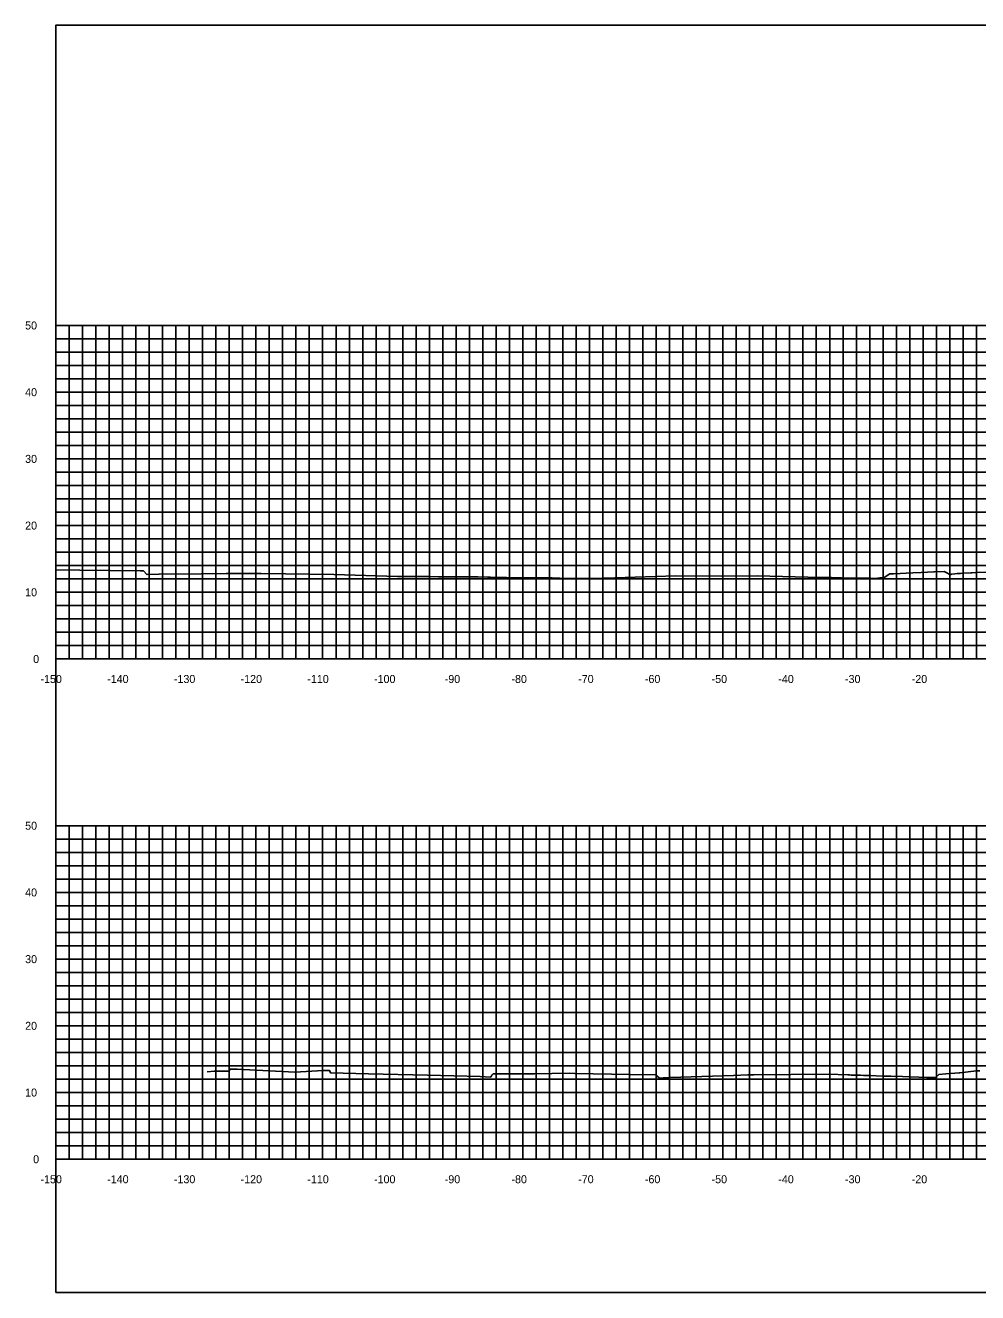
# Model space of a CAD drawing. Extents: x 1797714 to 1804825, y 249015 to 250269.
# Drawn here: x 1804149.6 to 1804292.3, y 249628.2 to 249818.2 of the extents above; entities that cross this region are included whole.
import ezdxf

# ---------------------------------------------------------------- set-up
doc = ezdxf.new("R2010")
doc.units = 0
for name, color, linetype in [('10', 7, 'Continuous'), ('31', 7, 'Continuous'), ('60', 7, 'Continuous'), ('Level 62', 7, 'Continuous'), ('M-ROADS', 7, 'Continuous')]:
    doc.layers.add(name, color=color, linetype=linetype)

msp = doc.modelspace()

# ---------------------------------------------------------------- linework, layer by layer
msp.add_lwpolyline([(1804154.16, 249628.17), (1804454.16, 249628.17), (1804454.16, 249818.17), (1804154.16, 249818.17)], close=True)
at = {"layer": '60'}
for p, q in [((1804154.1, 249773.17), (1804154.16, 249773.17)), ((1804154.16, 249723.17), (1804154.16, 249773.17)), ((1804154.1, 249763.17), (1804154.16, 249763.17)), ((1804154.1, 249753.17), (1804154.16, 249753.17)), ((1804154.1, 249743.17), (1804154.16, 249743.17)), ((1804154.1, 249733.17), (1804154.16, 249733.17)), ((1804154.1, 249723.17), (1804154.16, 249723.17)), ((1804154.16, 249723.17), (1804454.16, 249723.17)), ((1804154.16, 249723.11), (1804154.16, 249723.17)), ((1804164.16, 249723.11), (1804164.16, 249723.17)), ((1804174.16, 249723.11), (1804174.16, 249723.17)), ((1804184.16, 249723.11), (1804184.16, 249723.17)), ((1804194.16, 249723.11), (1804194.16, 249723.17)), ((1804204.16, 249723.11), (1804204.16, 249723.17)), ((1804214.16, 249723.11), (1804214.16, 249723.17)), ((1804224.16, 249723.11), (1804224.16, 249723.17)), ((1804234.16, 249723.11), (1804234.16, 249723.17)), ((1804244.16, 249723.11), (1804244.16, 249723.17)), ((1804254.16, 249723.11), (1804254.16, 249723.17)), ((1804264.16, 249723.11), (1804264.16, 249723.17)), ((1804274.16, 249723.11), (1804274.16, 249723.17)), ((1804284.16, 249723.11), (1804284.16, 249723.17)), ((1804154.1, 249698.17), (1804154.16, 249698.17)), ((1804154.16, 249648.17), (1804154.16, 249698.17)), ((1804154.1, 249688.17), (1804154.16, 249688.17)), ((1804154.1, 249678.17), (1804154.16, 249678.17)), ((1804154.1, 249668.17), (1804154.16, 249668.17)), ((1804154.1, 249658.17), (1804154.16, 249658.17)), ((1804154.1, 249648.17), (1804154.16, 249648.17)), ((1804154.16, 249648.17), (1804454.16, 249648.17)), ((1804154.16, 249648.11), (1804154.16, 249648.17)), ((1804164.16, 249648.11), (1804164.16, 249648.17)), ((1804174.16, 249648.11), (1804174.16, 249648.17)), ((1804184.16, 249648.11), (1804184.16, 249648.17)), ((1804194.16, 249648.11), (1804194.16, 249648.17)), ((1804204.16, 249648.11), (1804204.16, 249648.17)), ((1804214.16, 249648.11), (1804214.16, 249648.17)), ((1804224.16, 249648.11), (1804224.16, 249648.17)), ((1804234.16, 249648.11), (1804234.16, 249648.17)), ((1804244.16, 249648.11), (1804244.16, 249648.17)), ((1804254.16, 249648.11), (1804254.16, 249648.17)), ((1804264.16, 249648.11), (1804264.16, 249648.17)), ((1804274.16, 249648.11), (1804274.16, 249648.17)), ((1804284.16, 249648.11), (1804284.16, 249648.17))]:
    msp.add_line(p, q, dxfattribs=at)
at = {"layer": 'Level 62'}
for p, q in [((1804154.16, 249773.17), (1804454.16, 249773.17)), ((1804154.16, 249723.17), (1804154.16, 249773.17)), ((1804156.16, 249723.17), (1804156.16, 249773.17)), ((1804158.16, 249723.17), (1804158.16, 249773.17)), ((1804160.16, 249723.17), (1804160.16, 249773.17)), ((1804162.16, 249723.17), (1804162.16, 249773.17)), ((1804164.16, 249723.17), (1804164.16, 249773.17)), ((1804166.16, 249723.17), (1804166.16, 249773.17)), ((1804168.16, 249723.17), (1804168.16, 249773.17)), ((1804170.16, 249723.17), (1804170.16, 249773.17)), ((1804172.16, 249723.17), (1804172.16, 249773.17)), ((1804174.16, 249723.17), (1804174.16, 249773.17)), ((1804176.16, 249723.17), (1804176.16, 249773.17)), ((1804178.16, 249723.17), (1804178.16, 249773.17)), ((1804180.16, 249723.17), (1804180.16, 249773.17)), ((1804182.16, 249723.17), (1804182.16, 249773.17)), ((1804184.16, 249723.17), (1804184.16, 249773.17)), ((1804186.16, 249723.17), (1804186.16, 249773.17)), ((1804188.16, 249723.17), (1804188.16, 249773.17)), ((1804190.16, 249723.17), (1804190.16, 249773.17)), ((1804192.16, 249723.17), (1804192.16, 249773.17)), ((1804194.16, 249723.17), (1804194.16, 249773.17)), ((1804196.16, 249723.17), (1804196.16, 249773.17)), ((1804198.16, 249723.17), (1804198.16, 249773.17)), ((1804200.16, 249723.17), (1804200.16, 249773.17)), ((1804202.16, 249723.17), (1804202.16, 249773.17)), ((1804204.16, 249723.17), (1804204.16, 249773.17)), ((1804206.16, 249723.17), (1804206.16, 249773.17)), ((1804208.16, 249723.17), (1804208.16, 249773.17)), ((1804210.16, 249723.17), (1804210.16, 249773.17)), ((1804212.16, 249723.17), (1804212.16, 249773.17)), ((1804214.16, 249723.17), (1804214.16, 249773.17)), ((1804216.16, 249723.17), (1804216.16, 249773.17)), ((1804218.16, 249723.17), (1804218.16, 249773.17)), ((1804220.16, 249723.17), (1804220.16, 249773.17)), ((1804222.16, 249723.17), (1804222.16, 249773.17)), ((1804224.16, 249723.17), (1804224.16, 249773.17)), ((1804226.16, 249723.17), (1804226.16, 249773.17)), ((1804228.16, 249723.17), (1804228.16, 249773.17)), ((1804230.16, 249723.17), (1804230.16, 249773.17)), ((1804232.16, 249723.17), (1804232.16, 249773.17)), ((1804234.16, 249723.17), (1804234.16, 249773.17)), ((1804236.16, 249723.17), (1804236.16, 249773.17)), ((1804238.16, 249723.17), (1804238.16, 249773.17)), ((1804240.16, 249723.17), (1804240.16, 249773.17)), ((1804242.16, 249723.17), (1804242.16, 249773.17)), ((1804244.16, 249723.17), (1804244.16, 249773.17)), ((1804246.16, 249723.17), (1804246.16, 249773.17)), ((1804248.16, 249723.17), (1804248.16, 249773.17)), ((1804250.16, 249723.17), (1804250.16, 249773.17)), ((1804252.16, 249723.17), (1804252.16, 249773.17)), ((1804254.16, 249723.17), (1804254.16, 249773.17)), ((1804256.16, 249723.17), (1804256.16, 249773.17)), ((1804258.16, 249723.17), (1804258.16, 249773.17)), ((1804260.16, 249723.17), (1804260.16, 249773.17)), ((1804262.16, 249723.17), (1804262.16, 249773.17)), ((1804264.16, 249723.17), (1804264.16, 249773.17)), ((1804266.16, 249723.17), (1804266.16, 249773.17)), ((1804268.16, 249723.17), (1804268.16, 249773.17)), ((1804270.16, 249723.17), (1804270.16, 249773.17)), ((1804272.16, 249723.17), (1804272.16, 249773.17)), ((1804274.16, 249723.17), (1804274.16, 249773.17)), ((1804276.16, 249723.17), (1804276.16, 249773.17)), ((1804278.16, 249723.17), (1804278.16, 249773.17)), ((1804280.16, 249723.17), (1804280.16, 249773.17)), ((1804282.16, 249723.17), (1804282.16, 249773.17)), ((1804284.16, 249723.17), (1804284.16, 249773.17)), ((1804286.16, 249723.17), (1804286.16, 249773.17)), ((1804288.16, 249723.17), (1804288.16, 249773.17)), ((1804290.16, 249723.17), (1804290.16, 249773.17)), ((1804292.16, 249723.17), (1804292.16, 249773.17)), ((1804154.16, 249771.17), (1804454.16, 249771.17)), ((1804154.16, 249769.17), (1804454.16, 249769.17)), ((1804154.16, 249767.17), (1804454.16, 249767.17)), ((1804154.16, 249765.17), (1804454.16, 249765.17)), ((1804154.16, 249763.17), (1804454.16, 249763.17)), ((1804154.16, 249761.17), (1804454.16, 249761.17)), ((1804154.16, 249759.17), (1804454.16, 249759.17)), ((1804154.16, 249757.17), (1804454.16, 249757.17)), ((1804154.16, 249755.17), (1804454.16, 249755.17)), ((1804154.16, 249753.17), (1804454.16, 249753.17)), ((1804154.16, 249751.17), (1804454.16, 249751.17)), ((1804154.16, 249749.17), (1804454.16, 249749.17)), ((1804154.16, 249747.17), (1804454.16, 249747.17)), ((1804154.16, 249745.17), (1804454.16, 249745.17)), ((1804154.16, 249743.17), (1804454.16, 249743.17)), ((1804154.16, 249741.17), (1804454.16, 249741.17)), ((1804154.16, 249739.17), (1804454.16, 249739.17)), ((1804154.16, 249737.17), (1804454.16, 249737.17)), ((1804154.16, 249735.17), (1804454.16, 249735.17)), ((1804154.16, 249733.17), (1804454.16, 249733.17)), ((1804154.16, 249731.17), (1804454.16, 249731.17)), ((1804154.16, 249729.17), (1804454.16, 249729.17)), ((1804154.16, 249727.17), (1804454.16, 249727.17)), ((1804154.16, 249725.17), (1804454.16, 249725.17)), ((1804154.16, 249723.17), (1804454.16, 249723.17)), ((1804154.16, 249698.17), (1804454.16, 249698.17)), ((1804154.16, 249648.17), (1804154.16, 249698.17)), ((1804156.16, 249648.17), (1804156.16, 249698.17)), ((1804158.16, 249648.17), (1804158.16, 249698.17)), ((1804160.16, 249648.17), (1804160.16, 249698.17)), ((1804162.16, 249648.17), (1804162.16, 249698.17)), ((1804164.16, 249648.17), (1804164.16, 249698.17)), ((1804166.16, 249648.17), (1804166.16, 249698.17)), ((1804168.16, 249648.17), (1804168.16, 249698.17)), ((1804170.16, 249648.17), (1804170.16, 249698.17)), ((1804172.16, 249648.17), (1804172.16, 249698.17)), ((1804174.16, 249648.17), (1804174.16, 249698.17)), ((1804176.16, 249648.17), (1804176.16, 249698.17)), ((1804178.16, 249648.17), (1804178.16, 249698.17)), ((1804180.16, 249648.17), (1804180.16, 249698.17)), ((1804182.16, 249648.17), (1804182.16, 249698.17)), ((1804184.16, 249648.17), (1804184.16, 249698.17)), ((1804186.16, 249648.17), (1804186.16, 249698.17)), ((1804188.16, 249648.17), (1804188.16, 249698.17)), ((1804190.16, 249648.17), (1804190.16, 249698.17)), ((1804192.16, 249648.17), (1804192.16, 249698.17)), ((1804194.16, 249648.17), (1804194.16, 249698.17)), ((1804196.16, 249648.17), (1804196.16, 249698.17)), ((1804198.16, 249648.17), (1804198.16, 249698.17)), ((1804200.16, 249648.17), (1804200.16, 249698.17)), ((1804202.16, 249648.17), (1804202.16, 249698.17)), ((1804204.16, 249648.17), (1804204.16, 249698.17)), ((1804206.16, 249648.17), (1804206.16, 249698.17)), ((1804208.16, 249648.17), (1804208.16, 249698.17)), ((1804210.16, 249648.17), (1804210.16, 249698.17)), ((1804212.16, 249648.17), (1804212.16, 249698.17)), ((1804214.16, 249648.17), (1804214.16, 249698.17)), ((1804216.16, 249648.17), (1804216.16, 249698.17)), ((1804218.16, 249648.17), (1804218.16, 249698.17)), ((1804220.16, 249648.17), (1804220.16, 249698.17)), ((1804222.16, 249648.17), (1804222.16, 249698.17)), ((1804224.16, 249648.17), (1804224.16, 249698.17)), ((1804226.16, 249648.17), (1804226.16, 249698.17)), ((1804228.16, 249648.17), (1804228.16, 249698.17)), ((1804230.16, 249648.17), (1804230.16, 249698.17)), ((1804232.16, 249648.17), (1804232.16, 249698.17)), ((1804234.16, 249648.17), (1804234.16, 249698.17)), ((1804236.16, 249648.17), (1804236.16, 249698.17)), ((1804238.16, 249648.17), (1804238.16, 249698.17)), ((1804240.16, 249648.17), (1804240.16, 249698.17)), ((1804242.16, 249648.17), (1804242.16, 249698.17)), ((1804244.16, 249648.17), (1804244.16, 249698.17)), ((1804246.16, 249648.17), (1804246.16, 249698.17)), ((1804248.16, 249648.17), (1804248.16, 249698.17)), ((1804250.16, 249648.17), (1804250.16, 249698.17)), ((1804252.16, 249648.17), (1804252.16, 249698.17)), ((1804254.16, 249648.17), (1804254.16, 249698.17)), ((1804256.16, 249648.17), (1804256.16, 249698.17)), ((1804258.16, 249648.17), (1804258.16, 249698.17)), ((1804260.16, 249648.17), (1804260.16, 249698.17)), ((1804262.16, 249648.17), (1804262.16, 249698.17)), ((1804264.16, 249648.17), (1804264.16, 249698.17)), ((1804266.16, 249648.17), (1804266.16, 249698.17)), ((1804268.16, 249648.17), (1804268.16, 249698.17)), ((1804270.16, 249648.17), (1804270.16, 249698.17)), ((1804272.16, 249648.17), (1804272.16, 249698.17)), ((1804274.16, 249648.17), (1804274.16, 249698.17)), ((1804276.16, 249648.17), (1804276.16, 249698.17)), ((1804278.16, 249648.17), (1804278.16, 249698.17)), ((1804280.16, 249648.17), (1804280.16, 249698.17)), ((1804282.16, 249648.17), (1804282.16, 249698.17)), ((1804284.16, 249648.17), (1804284.16, 249698.17)), ((1804286.16, 249648.17), (1804286.16, 249698.17)), ((1804288.16, 249648.17), (1804288.16, 249698.17)), ((1804290.16, 249648.17), (1804290.16, 249698.17)), ((1804292.16, 249648.17), (1804292.16, 249698.17)), ((1804154.16, 249696.17), (1804454.16, 249696.17)), ((1804154.16, 249694.17), (1804454.16, 249694.17)), ((1804154.16, 249692.17), (1804454.16, 249692.17)), ((1804154.16, 249690.17), (1804454.16, 249690.17)), ((1804154.16, 249688.17), (1804454.16, 249688.17)), ((1804154.16, 249686.17), (1804454.16, 249686.17)), ((1804154.16, 249684.17), (1804454.16, 249684.17)), ((1804154.16, 249682.17), (1804454.16, 249682.17)), ((1804154.16, 249680.17), (1804454.16, 249680.17)), ((1804154.16, 249678.17), (1804454.16, 249678.17)), ((1804154.16, 249676.17), (1804454.16, 249676.17)), ((1804154.16, 249674.17), (1804454.16, 249674.17)), ((1804154.16, 249672.17), (1804454.16, 249672.17)), ((1804154.16, 249670.17), (1804454.16, 249670.17)), ((1804154.16, 249668.17), (1804454.16, 249668.17)), ((1804154.16, 249666.17), (1804454.16, 249666.17)), ((1804154.16, 249664.17), (1804454.16, 249664.17)), ((1804154.16, 249662.17), (1804454.16, 249662.17)), ((1804154.16, 249660.17), (1804454.16, 249660.17)), ((1804154.16, 249658.17), (1804454.16, 249658.17)), ((1804154.16, 249656.17), (1804454.16, 249656.17)), ((1804154.16, 249654.17), (1804454.16, 249654.17)), ((1804154.16, 249652.17), (1804454.16, 249652.17)), ((1804154.16, 249650.17), (1804454.16, 249650.17)), ((1804154.16, 249648.17), (1804454.16, 249648.17))]:
    msp.add_line(p, q, dxfattribs=at)
at = {"layer": 'M-ROADS'}
for points in [[(1804154.16, 249736.56), (1804157.75, 249736.51), (1804166.86, 249736.41), (1804167.29, 249736.4), (1804167.82, 249735.86), (1804167.84, 249735.85), (1804169.58, 249735.9), (1804169.65, 249735.9), (1804175.96, 249735.95), (1804179.69, 249735.97), (1804181.06, 249735.98), (1804181.59, 249735.98), (1804182.28, 249735.98), (1804184.95, 249735.98), (1804195.83, 249735.82), (1804205.36, 249735.56), (1804206.29, 249735.55), (1804207.38, 249735.54), (1804210.09, 249735.52), (1804211.53, 249735.51), (1804214.2, 249735.47), (1804215.87, 249735.48), (1804217.04, 249735.48), (1804217.24, 249735.47), (1804217.42, 249735.47), (1804218.89, 249735.43), (1804219.34, 249735.42), (1804220.26, 249735.4), (1804220.61, 249735.39), (1804221.33, 249735.38), (1804221.47, 249735.37), (1804221.71, 249735.37), (1804223.19, 249735.35), (1804223.3, 249735.35), (1804224.04, 249735.35), (1804224.4, 249735.34), (1804225.71, 249735.34), (1804226.7, 249735.34), (1804227.22, 249735.33), (1804228.36, 249735.33), (1804228.58, 249735.33), (1804230.85, 249735.25), (1804230.89, 249735.25), (1804230.92, 249735.25), (1804232.52, 249735.22), (1804232.63, 249735.23), (1804234.18, 249735.25), (1804237.97, 249735.36), (1804247.08, 249735.63), (1804254.02, 249735.59), (1804259.29, 249735.62), (1804268.8, 249735.4), (1804269.28, 249735.39), (1804269.82, 249735.38), (1804270.41, 249735.38), (1804271.07, 249735.36), (1804271.82, 249735.35), (1804271.94, 249735.35), (1804274.33, 249735.28), (1804274.8, 249735.27), (1804274.8, 249735.27), (1804275.01, 249735.28), (1804275.43, 249735.31), (1804276.08, 249735.3), (1804276.22, 249735.28), (1804276.35, 249735.27), (1804276.68, 249735.25), (1804276.78, 249735.25), (1804276.88, 249735.26), (1804277.31, 249735.3), (1804278.45, 249735.42), (1804278.65, 249735.6), (1804279.18, 249735.93), (1804279.73, 249735.96), (1804280.71, 249736), (1804281.62, 249736.04), (1804282.62, 249736.08), (1804283.88, 249736.13), (1804285.76, 249736.22), (1804285.88, 249736.23), (1804287.31, 249736.3), (1804287.62, 249736.14), (1804288.15, 249735.84), (1804288.31, 249735.86), (1804288.42, 249735.87), (1804288.9, 249735.92), (1804289.26, 249735.97), (1804289.36, 249735.98), (1804289.79, 249736.01), (1804290.07, 249736.05), (1804290.18, 249736.06), (1804291.3, 249736.09), (1804291.45, 249736.09), (1804292.22, 249736.13), (1804299.94, 249736.34)], [(1804176.85, 249661.29), (1804177.92, 249661.36), (1804179.63, 249661.36), (1804180.16, 249661.36), (1804180.26, 249661.66), (1804180.27, 249661.67), (1804180.29, 249661.67), (1804181.35, 249661.68), (1804189.99, 249661.23), (1804194.26, 249661.47), (1804194.87, 249661.46), (1804195.19, 249661.45), (1804195.22, 249661.37), (1804195.35, 249661.12), (1804201.04, 249660.97), (1804209.9, 249660.77), (1804217.78, 249660.57), (1804218.5, 249660.52), (1804219.35, 249660.49), (1804219.53, 249660.75), (1804219.74, 249660.99), (1804225.89, 249660.97), (1804231.1, 249661.05), (1804231.94, 249661), (1804240.2, 249660.89), (1804244.11, 249660.81), (1804244.26, 249660.65), (1804244.67, 249660.32), (1804245.21, 249660.35), (1804246.27, 249660.42), (1804255.73, 249660.74), (1804257.9, 249660.82), (1804258.77, 249660.83), (1804269.92, 249660.92), (1804272.87, 249660.81), (1804273.02, 249660.8), (1804273.19, 249660.8), (1804273.38, 249660.79), (1804273.6, 249660.78), (1804273.84, 249660.78), (1804274.11, 249660.77), (1804274.43, 249660.76), (1804274.79, 249660.75), (1804275.22, 249660.73), (1804275.73, 249660.72), (1804276.35, 249660.7), (1804277.11, 249660.67), (1804278.08, 249660.64), (1804279.34, 249660.6), (1804281.06, 249660.55), (1804283.54, 249660.47), (1804284.73, 249660.43), (1804284.89, 249660.43), (1804285.18, 249660.42), (1804285.36, 249660.42), (1804285.48, 249660.41), (1804285.56, 249660.41), (1804285.63, 249660.41), (1804285.68, 249660.41), (1804285.72, 249660.41), (1804285.75, 249660.41), (1804285.78, 249660.41), (1804285.81, 249660.41), (1804285.83, 249660.41), (1804286.04, 249660.4), (1804286.46, 249660.83), (1804286.54, 249660.89), (1804287.59, 249660.96), (1804289.57, 249661.13), (1804289.68, 249661.14), (1804292.16, 249661.4), (1804292.26, 249661.4), (1804292.67, 249661.4)]]:
    msp.add_lwpolyline(points, dxfattribs=at)

# ---------------------------------------------------------------- texts
at = {"layer": '10'}
for s, p in [('-150', (1804151.86, 249719.57)), ('-140', (1804161.86, 249719.57)), ('-130', (1804171.86, 249719.57)), ('-120', (1804181.86, 249719.57)), ('-110', (1804191.86, 249719.57)), ('-100', (1804201.86, 249719.57)), ('-90', (1804212.46, 249719.57)), ('-80', (1804222.46, 249719.57)), ('-70', (1804232.46, 249719.57)), ('-60', (1804242.46, 249719.57)), ('-50', (1804252.46, 249719.57)), ('-40', (1804262.46, 249719.57)), ('-30', (1804272.46, 249719.57)), ('-20', (1804282.46, 249719.57)), ('-150', (1804151.86, 249644.57)), ('-140', (1804161.86, 249644.57)), ('-130', (1804171.86, 249644.57)), ('-120', (1804181.86, 249644.57)), ('-110', (1804191.86, 249644.57)), ('-100', (1804201.86, 249644.57)), ('-90', (1804212.46, 249644.57)), ('-80', (1804222.46, 249644.57)), ('-70', (1804232.46, 249644.57)), ('-60', (1804242.46, 249644.57)), ('-50', (1804252.46, 249644.57)), ('-40', (1804262.46, 249644.57)), ('-30', (1804272.46, 249644.57)), ('-20', (1804282.46, 249644.57))]:
    msp.add_text(s, height=1.2, dxfattribs=at).set_placement(p)
at = {"layer": '31'}
for s, p in [('50', (1804149.56, 249772.57)), ('40', (1804149.56, 249762.57)), ('30', (1804149.56, 249752.57)), ('20', (1804149.56, 249742.57)), ('10', (1804149.56, 249732.57)), ('0', (1804150.76, 249722.57)), ('50', (1804149.56, 249697.57)), ('40', (1804149.56, 249687.57)), ('30', (1804149.56, 249677.57)), ('20', (1804149.56, 249667.57)), ('10', (1804149.56, 249657.57)), ('0', (1804150.76, 249647.57))]:
    msp.add_text(s, height=1.2, dxfattribs=at).set_placement(p)
at = {"layer": '60'}
for p in [(1804154.16, 249723.17), (1804154.16, 249648.17)]:
    msp.add_text('-', height=0.0001, dxfattribs=at).set_placement(p)

doc.saveas('drawing.dxf')
